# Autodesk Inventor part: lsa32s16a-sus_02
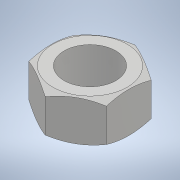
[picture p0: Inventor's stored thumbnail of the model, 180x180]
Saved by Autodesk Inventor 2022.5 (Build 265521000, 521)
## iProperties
Part Number: lsa32s16a-sus_02
Material: 一般
Document SubType Name: Modeling
Designer: ImaoCorp
Density: 1 g/cm^3
Appearance: 既定
Author: ImaoCorp
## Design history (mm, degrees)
feature "lsa32s16a-sus_02"
node "ソリッド1"
